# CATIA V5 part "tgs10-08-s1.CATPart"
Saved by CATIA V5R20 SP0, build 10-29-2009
Part number: TGS10-08-S1
Revision: 1
Definition: design
Nomenclature: TGS10-08-S1
Source: made
Description: NOT SPECIFIED
Bounding box of the stored display mesh (mm): x -22 to 0.8, y 0 to 10, z -4 to 4
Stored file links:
  C:\Users\Raffaele\Desktop\3D X SITO CF\I-MOLD\TGS-S1\tgs10-s1.step\tgs10-08-s1.CATPart
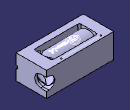
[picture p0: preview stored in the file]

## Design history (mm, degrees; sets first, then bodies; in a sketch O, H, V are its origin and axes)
Set1
  Line1 "LINE #4115": stored without definition
  DatumCurve1 "COMPOSITE_CURVE #4186"
  DatumCurve2 "COMPOSITE_CURVE #4237"
  DatumCurve3 "COMPOSITE_CURVE #4316"
  DatumCurve4 "COMPOSITE_CURVE #4359"
  DatumCurve5 "COMPOSITE_CURVE #4588"
  DatumCurve6 "COMPOSITE_CURVE #4730"
  DatumCurve7 "COMPOSITE_CURVE #4757"
  DatumCurve8 "COMPOSITE_CURVE #4815"
  DatumCurve9 "COMPOSITE_CURVE #4872"
  DatumCurve10 "COMPOSITE_CURVE #4901"
  DatumSurface1 "OPEN_SHELL #4105"
Body1 "MANIFOLD_SOLID_BREP #4106" (main body)
  Solid1: solid without history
